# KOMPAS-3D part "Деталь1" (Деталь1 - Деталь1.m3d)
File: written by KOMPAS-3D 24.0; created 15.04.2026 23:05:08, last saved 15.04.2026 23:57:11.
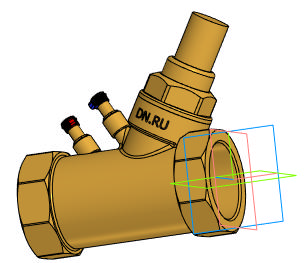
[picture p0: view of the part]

Document properties: Автор: tyuri; Полное имя файла: D:\Аутсорс\VB0000P-T Клапан балансировочный статический DN.ru\DN40\Исходные данные\Деталь1 - Деталь1.m3d

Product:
- Body: Твердое тело1  | qty 1
    Масса: 1.432107
- Part/product: Деталь1
    Масса: 1.432107
    additional columns: Типовые

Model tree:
1. Твердое тело1  (labels: Твердое тело1)
2. Изменить положение граней:1  (labels: Грань.Твердое тело1)
     Расстояние = 4.5
3. Изменить положение граней:2  (labels: Грань.Твердое тело1)
     Расстояние = 4.5
4. Эскиз:1  (labels: Грань.Твердое тело1)
5. Элемент выдавливания:1  (labels: Грань.Твердое тело1)
     Расстояние 2 = -34.4162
